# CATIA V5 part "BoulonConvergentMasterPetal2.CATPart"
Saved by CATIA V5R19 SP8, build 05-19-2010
Part number: BoulonConvergentMasterPetal2
Bounding box of the stored display mesh (mm): x -28 to 24, y 522 to 538, z 592 to 608
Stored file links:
  G:\EU_thinkMotion\CFAO_2010\MMS_groupe3\MMS_groupe3\A reprendre\fovide\fovide\BoulonConvergentMasterPetal2.CATPart
  C:\Users\Rodger\Desktop\Part11.CATPart
  G:\EU_thinkMotion\CFAO_2010\MMS_groupe3\MMS_groupe3\A reprendre\fovide\fovide\fovide.CATProduct
  G:\EU_thinkMotion\CFAO_2010\MMS_groupe3\MMS_groupe3\A reprendre\fovide\fovide\Convergent Master Petal 4.CATPart
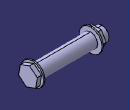
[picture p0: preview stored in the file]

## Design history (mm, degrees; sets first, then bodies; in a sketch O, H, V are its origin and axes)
Parameters
  Diametre = 10 mm
  Longueur = 40 mm
Set1
  DatumSurface1: linked copy from another document
  Point1: linked copy from another document
Body1 (main body)
Body2
  Sketch1 on DatumSurface1, origin (20, 0, 20), H (0, 0, -1), V (0, 1, 0)
    circle A1 centre (-580, 530) radius 8
    point P1 (-580, 530)
    reference projected point E1 (-580, 530) from Point1
    radius A1 = 8 {= Diametre *8/10}
    coincidence: P1 E1
  Pad1: profile Sketch1, direction (1, 0, 0), length 1
  Sketch2 on end face of Pad1, origin (21, 0, 22), H (0, 0, -1), V (0, 1, 0)
    point P1 (-578, 530)
    point P2 (-575.5061, 523.4593)
    point P3 (-571.0887, 528.8894)
    point P4 (-573.5825, 535.4301)
    point P5 (-580.4939, 536.5407)
    point P6 (-584.9113, 531.1106)
    point P7 (-582.4175, 524.5699)
    point P8 (-573.2974, 526.1744)
    line L1 (-575.5061, 523.4593) -> (-571.0887, 528.8894)
    line L2 (-571.0887, 528.8894) -> (-573.5825, 535.4301)
    line L3 (-573.5825, 535.4301) -> (-580.4939, 536.5407)
    line L4 (-580.4939, 536.5407) -> (-584.9113, 531.1106)
    line L5 (-584.9113, 531.1106) -> (-582.4175, 524.5699)
    line L6 (-582.4175, 524.5699) -> (-575.5061, 523.4593)
    construction line L7 (-578, 530) -> (-573.2974, 526.1744)
    construction circle A1 centre (-578, 530) radius 7
    construction arc A2 centre (-584.9113, 531.1106) radius 7 from (-580.4939, 536.5407) to (-582.4175, 524.5699) cw
    construction arc A3 centre (-571.0887, 528.8894) radius 7 from (-573.5825, 535.4301) to (-575.5061, 523.4593) ccw
    reference projected point E1 (-578, 530) from Point1
    radius A1 = 7 {= Diametre *7/10}
    coincidence: A1 P2, A1 P3, A1 P4, A1 P5, A1 P6, A1 P7, A2 P1, A3 P1, P1 E1
    midpoint: P8 L1
    parallelism: L1 L4
  Pad2: profile Sketch2, direction (1, 0, 0), length 3
  Sketch3 on start face of Pad1, origin (20, 0, 20), H (0, 0, -1), V (0, -1, 0)
    circle A1 centre (-580, -530) radius 5
    point P1 (-580, -530)
    reference projected point E1 (-580, -530) from Point1
    radius A1 = 5 {= Diametre /2}
    coincidence: P1 E1
  Pad3: profile Sketch3, direction (-1, 0, 0), length 40 {= Longueur}
  Sketch4 on end face of Pad3, origin (-20, 0, -60), H (0, 0, -1), V (0, -1, 0)
    circle A1 centre (-660, -530) radius 8
    point P1 (-660, -530)
    reference projected point E1 (-660, -530) from Point1
    radius A1 = 8 {= Diametre *8/10}
    coincidence: P1 E1
  Pad4: profile Sketch4, direction (-1, 0, 0), length 1
  Sketch5 on end face of Pad4, origin (-21, 0, -62), H (0, 0, -1), V (0, -1, 0)
    point P1 (-662, -530)
    point P2 (-662.0478, -536.9998)
    point P3 (-655.9619, -533.5413)
    point P4 (-655.9141, -526.5415)
    point P5 (-661.9522, -523.0002)
    point P6 (-668.0381, -526.4587)
    point P7 (-668.0859, -533.4585)
    point P8 (-659.0048, -535.2706)
    line L1 (-662.0478, -536.9998) -> (-655.9619, -533.5413)
    line L2 (-655.9619, -533.5413) -> (-655.9141, -526.5415)
    line L3 (-655.9141, -526.5415) -> (-661.9522, -523.0002)
    line L4 (-661.9522, -523.0002) -> (-668.0381, -526.4587)
    line L5 (-668.0381, -526.4587) -> (-668.0859, -533.4585)
    line L6 (-668.0859, -533.4585) -> (-662.0478, -536.9998)
    construction line L7 (-662, -530) -> (-659.0048, -535.2706)
    construction circle A1 centre (-662, -530) radius 7
    construction arc A2 centre (-668.0381, -526.4587) radius 7 from (-661.9522, -523.0002) to (-668.0859, -533.4585) cw
    construction arc A3 centre (-655.9619, -533.5413) radius 7 from (-655.9141, -526.5415) to (-662.0478, -536.9998) ccw
    reference projected point E1 (-662, -530) from Point1
    radius A1 = 7 {= Diametre *7/10}
    coincidence: A1 P2, A1 P3, A1 P4, A1 P5, A1 P6, A1 P7, A2 P1, A3 P1, P1 E1
    midpoint: P8 L1
    parallelism: L1 L4
  Pad5: profile Sketch5, direction (-1, 0, 0), length 3
  Sketch6 on end face of Pad5, origin (-24, 0, -68), H (0, 0, -1), V (0, -1, 0)
    circle A1 centre (-668, -530) radius 5
    point P1 (-668, -530)
    reference projected point E1 (-668, -530) from Point1
    radius A1 = 5 {= Diametre /2}
    coincidence: P1 E1
  Pad6: profile Sketch6, direction (-1, 0, 0), length 4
